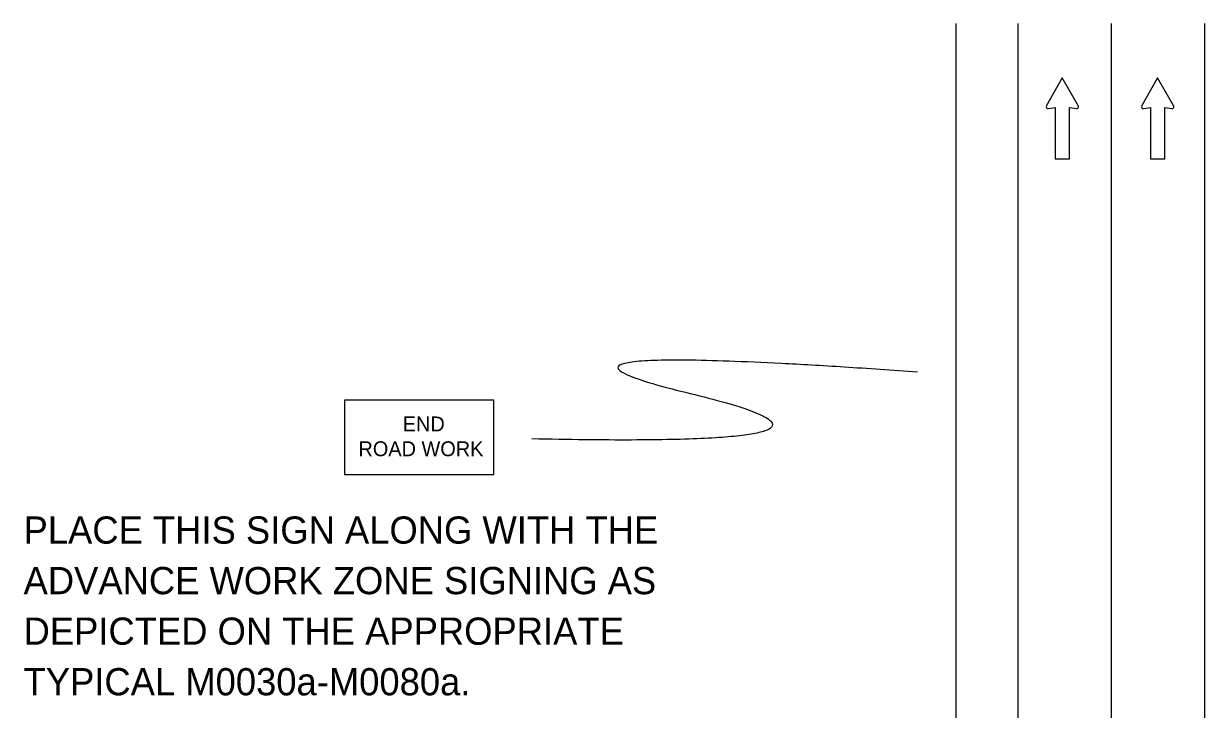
# Model space of a CAD drawing. Extents: x 16745 to 18475, y 7012 to 8195.
# Drawn here: x 16747.5 to 17051.4, y 8015 to 8191.4 of the extents above; entities that cross this region are included whole.
import ezdxf

# ---------------------------------------------------------------- set-up
doc = ezdxf.new("R2010")
doc.units = 0
for name, color, linetype in [('ALI_LEGAL_EX', 7, 'Continuous'), ('MT_SCRATCH_LEVEL_E', 7, 'Continuous'), ('PAVT_EDGE_EX', 7, 'Continuous'), ('TRAFFIC_SIGNS_PR', 7, 'Continuous')]:
    doc.layers.add(name, color=color, linetype=linetype)

msp = doc.modelspace()

# ---------------------------------------------------------------- linework, layer by layer
at = {"layer": 'ALI_LEGAL_EX'}
for p, q in [((17027.37, 8191.42), (17027.37, 7362.23)), ((17051.37, 8191.42), (17051.37, 7362.23)), ((17051.37, 8191.42), (17051.37, 7362.23))]:
    msp.add_line(p, q, dxfattribs=at)
for points in [[(17027.37, 8191.42), (17027.37, 8166.42)], [(17051.37, 8191.42), (17051.37, 8166.42)], [(17027.37, 8091.42), (17027.37, 8066.42)], [(17051.37, 8091.42), (17051.37, 8066.42)]]:
    msp.add_lwpolyline(points, dxfattribs=at)
at = {"layer": 'MT_SCRATCH_LEVEL_E'}
for p, q in [((17014.8, 8177.47), (17010.69, 8170.23)), ((17014.8, 8177.47), (17010.69, 8170.23)), ((17018.95, 8170.23), (17014.8, 8177.47)), ((17018.95, 8170.23), (17014.8, 8177.47)), ((17039.33, 8177.47), (17035.22, 8170.23)), ((17039.33, 8177.47), (17035.22, 8170.23)), ((17043.48, 8170.23), (17039.33, 8177.47)), ((17043.48, 8170.23), (17039.33, 8177.47)), ((17011.17, 8169.55), (17012.95, 8169.86)), ((17011.17, 8169.55), (17012.95, 8169.86)), ((17012.95, 8169.86), (17012.95, 8156.6)), ((17012.95, 8169.86), (17012.95, 8156.6)), ((17016.69, 8156.6), (17016.69, 8169.86)), ((17016.69, 8169.86), (17018.47, 8169.55)), ((17016.69, 8156.6), (17016.69, 8169.86)), ((17016.69, 8169.86), (17018.47, 8169.55)), ((17035.7, 8169.55), (17037.48, 8169.86)), ((17035.7, 8169.55), (17037.48, 8169.86)), ((17037.48, 8169.86), (17037.48, 8156.6)), ((17037.48, 8169.86), (17037.48, 8156.6)), ((17041.22, 8156.6), (17041.22, 8169.86)), ((17041.22, 8169.86), (17043, 8169.55)), ((17041.22, 8156.6), (17041.22, 8169.86)), ((17041.22, 8169.86), (17043, 8169.55)), ((17012.95, 8156.6), (17016.69, 8156.6)), ((17012.95, 8156.6), (17016.69, 8156.6)), ((17037.48, 8156.6), (17041.22, 8156.6)), ((17037.48, 8156.6), (17041.22, 8156.6))]:
    msp.add_line(p, q, dxfattribs=at)
for centre, start, end in [((17011.1, 8170), 150.4248, 279.9638), ((17011.1, 8170), 150.4248, 279.9638), ((17018.54, 8170), 260.0362, 29.7731), ((17018.54, 8170), 260.0362, 29.7731), ((17035.63, 8170), 150.4248, 279.9638), ((17035.63, 8170), 150.4248, 279.9638), ((17043.07, 8170), 260.0362, 29.7731), ((17043.07, 8170), 260.0362, 29.7731)]:
    msp.add_arc(centre, 0.463, start, end, dxfattribs=at)
at = {"layer": 'PAVT_EDGE_EX'}
for p, q in [((16987.37, 8191.42), (16987.37, 7362.23)), ((17003.37, 8191.42), (17003.37, 7362.23)), ((17003.37, 8191.42), (17003.37, 7362.23))]:
    msp.add_line(p, q, dxfattribs=at)
at = {"layer": 'TRAFFIC_SIGNS_PR'}
msp.add_lwpolyline([(16830.08, 8075.41), (16868.48, 8075.41), (16868.48, 8094.61), (16830.08, 8094.61)], close=True, dxfattribs=at)
msp.add_open_spline([(16977.58, 8101.78), (16862.35, 8110.02), (16976.26, 8082.44), (16878.32, 8084.61)], degree=2, dxfattribs=at)

# ---------------------------------------------------------------- texts
for s, height, p in [('END', 3.831, (16845.08, 8086.54)), ('ROAD WORK', 3.831, (16833.69, 8080.15)), ('PLACE THIS SIGN ALONG WITH THE', 7, (16747.51, 8057.66)), ('ADVANCE WORK ZONE SIGNING AS', 7, (16747.51, 8044.66)), ('DEPICTED ON THE APPROPRIATE', 7, (16747.51, 8031.66)), ('TYPICAL M0030a-M0080a.', 7, (16747.51, 8018.65))]:
    msp.add_text(s, height=height, dxfattribs=at).set_placement(p)

doc.saveas('drawing.dxf')
